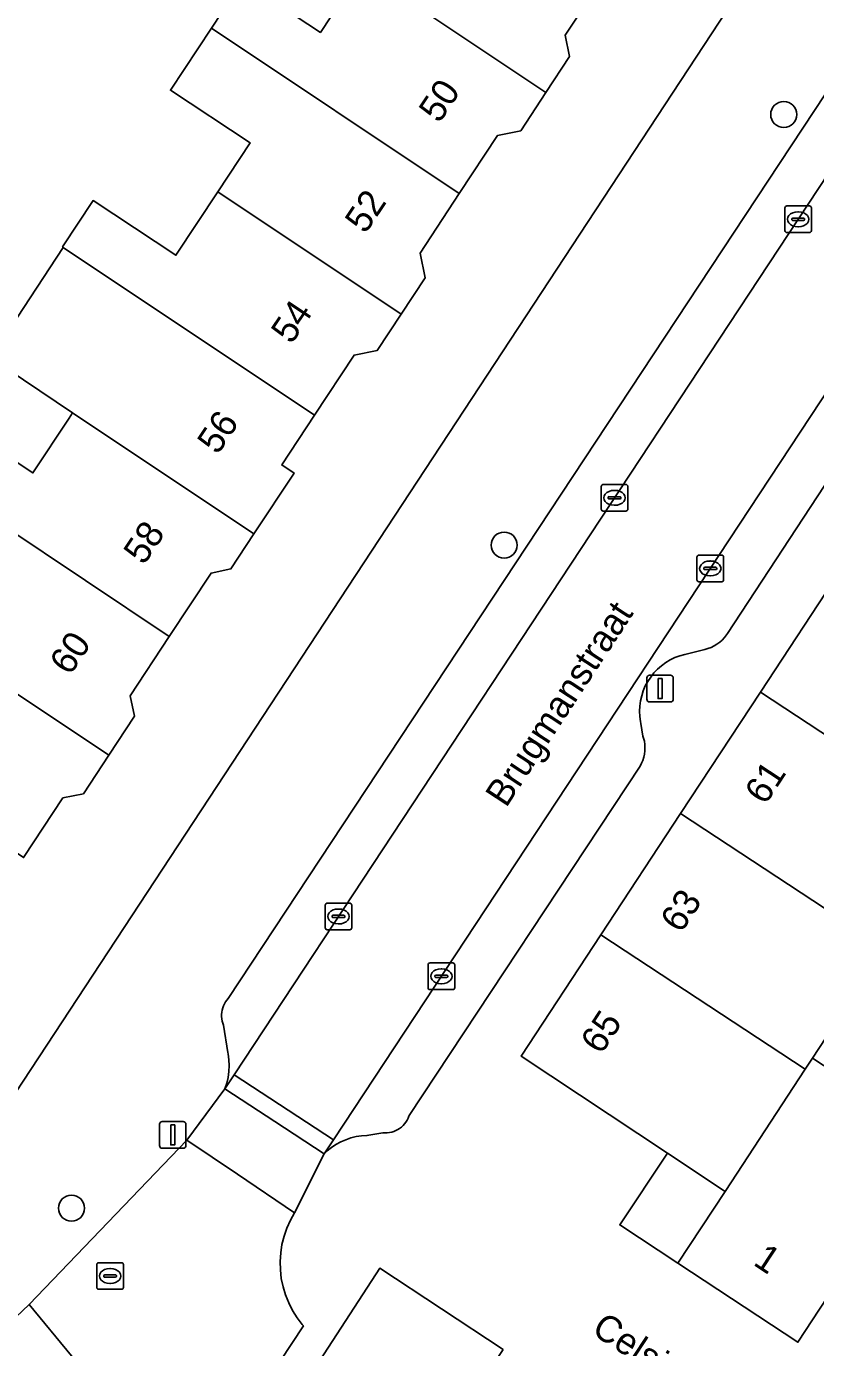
# Model space of a CAD drawing. Extents: x 159279 to 160377, y 384531 to 385888.
# Drawn here: x 159545.01 to 159574.65, y 385140.99 to 385190.61 of the extents above; entities that cross this region are included whole.
import ezdxf

# ---------------------------------------------------------------- set-up
doc = ezdxf.new("R2010")
doc.units = 0
for name, color, linetype in [('IMGEO_Boom', 7, 'Continuous'), ('IMGEO_Erf', 7, 'Continuous'), ('IMGEO_Kolk', 7, 'Continuous'), ('IMGEO_Lichtmast', 7, 'Continuous'), ('IMGEO_Openbare_ruimte_label', 7, 'Continuous'), ('IMGEO_Pand', 7, 'Continuous'), ('IMGEO_Pand_nummerreeks', 7, 'Continuous'), ('IMGEO_Parkeervlak_open', 7, 'Continuous'), ('IMGEO_Rijbaan_lokaal_open', 7, 'Continuous'), ('IMGEO_Rioolput', 7, 'Continuous'), ('IMGEO_Voetpad_open', 7, 'Continuous')]:
    doc.layers.add(name, color=color, linetype=linetype)

msp = doc.modelspace()

# ---------------------------------------------------------------- linework, layer by layer
at = {"layer": 'IMGEO_Boom'}
for centre in [(159573.455, 385187.303), (159562.957, 385171.13), (159546.706, 385146.226)]:
    msp.add_circle(centre, 0.489, dxfattribs=at)
at = {"layer": 'IMGEO_Erf'}
for points in [[(159535.013, 385135.989), (159573.94, 385195.196)], [(159542.165, 385175.88), (159545.258, 385173.842), (159546.615, 385175.901), (159546.747, 385176.101), (159543.665, 385178.161), (159546.4, 385182.31), (159546.373, 385182.328), (159547.52, 385184.068), (159550.63, 385182.019), (159552.2, 385184.401), (159553.414, 385186.243), (159550.423, 385188.213), (159551.959, 385190.544), (159553.128, 385192.317), (159556.057, 385190.387), (159557.613, 385192.749)], [(159566.634, 385192.38), (159565.25, 385190.281), (159565.415, 385189.479), (159564.526, 385188.13), (159563.58, 385186.695), (159562.71, 385186.516), (159561.27, 385184.331), (159559.799, 385182.098), (159559.989, 385181.172), (159559.087, 385179.803), (159558.191, 385178.443), (159557.322, 385178.265), (159555.833, 385176.006), (159554.604, 385174.141), (159555.067, 385173.836), (159553.559, 385171.548), (159552.694, 385170.235), (159551.949, 385170.082), (159550.378, 385167.697), (159548.911, 385165.471), (159549.07, 385164.7), (159548.106, 385163.236), (159547.154, 385161.792), (159546.382, 385161.634), (159544.907, 385159.396)], [(159579.919, 385180.874), (159571.346, 385167.81), (159571.309, 385167.756), (159571.23, 385167.657), (159571.143, 385167.565), (159571.049, 385167.482), (159570.947, 385167.407), (159570.839, 385167.342), (159570.725, 385167.287), (159570.607, 385167.242), (159570.486, 385167.208), (159569.738, 385167.026), (159569.549, 385166.973), (159569.366, 385166.903), (159569.189, 385166.818), (159569.021, 385166.717), (159568.863, 385166.601), (159568.715, 385166.471), (159568.58, 385166.329), (159568.458, 385166.176), (159568.35, 385166.012), (159568.257, 385165.839), (159568.18, 385165.659), (159568.12, 385165.472), (159568.076, 385165.281), (159568.05, 385165.086), (159568.041, 385164.89), (159568.049, 385164.694), (159568.076, 385164.5), (159568.09, 385164.427), (159568.168, 385163.957), (159568.192, 385163.882), (159568.22, 385163.764), (159568.237, 385163.643), (159568.244, 385163.522), (159568.24, 385163.401), (159568.225, 385163.28), (159568.199, 385163.162), (159568.163, 385163.046), (159568.116, 385162.934), (159568.06, 385162.826), (159559.386, 385149.711), (159559.376, 385149.681), (159559.346, 385149.604), (159559.308, 385149.529), (159559.264, 385149.458), (159559.214, 385149.392), (159559.158, 385149.33), (159559.097, 385149.273), (159559.031, 385149.223), (159558.961, 385149.178), (159558.887, 385149.139), (159558.81, 385149.108), (159558.731, 385149.083), (159558.649, 385149.066), (159558.566, 385149.056), (159558.483, 385149.053), (159558.4, 385149.058), (159557.804, 385148.953), (159557.6, 385148.942), (159557.398, 385148.912), (159557.199, 385148.864), (159557.006, 385148.799), (159556.819, 385148.717), (159556.64, 385148.618), (159556.47, 385148.504), (159556.312, 385148.375), (159556.2, 385148.269), (159555.083, 385146.052), (159554.926, 385145.772), (159554.794, 385145.479), (159554.689, 385145.176), (159554.612, 385144.865), (159554.563, 385144.547), (159554.542, 385144.227), (159554.55, 385143.906), (159554.586, 385143.587), (159554.651, 385143.273), (159554.744, 385142.966), (159554.864, 385142.668), (159555.01, 385142.382), (159555.181, 385142.11), (159555.375, 385141.855), (159555.415, 385141.808), (159553.225, 385138.493)], [(159574.804, 385142.432), (159573.988, 385141.19), (159569.482, 385144.159), (159567.296, 385145.599), (159569.09, 385148.289), (159563.593, 385151.939), (159566.588, 385156.495), (159569.583, 385161.052), (159572.578, 385165.608), (159575.573, 385170.164)], [(159577.258, 385156.006), (159574.54, 385151.865), (159579.054, 385148.896)], [(159553.263, 385136.243), (159558.284, 385143.967), (159562.915, 385140.917)]]:
    msp.add_lwpolyline(points, dxfattribs=at)
at = {"layer": 'IMGEO_Kolk'}
for p, q in [((159573.496, 385182.942), (159573.496, 385183.794)), ((159573.571, 385183.868), (159574.423, 385183.868)), ((159574.497, 385183.794), (159574.497, 385182.942)), ((159573.755, 385183.362), (159573.755, 385183.374)), ((159574.193, 385183.325), (159573.795, 385183.325)), ((159573.798, 385183.411), (159574.196, 385183.411)), ((159573.984, 385183.648), (159574.009, 385183.648)), ((159574.239, 385183.374), (159574.239, 385183.362)), ((159574.423, 385182.868), (159573.571, 385182.868)), ((159574.007, 385183.088), (159573.982, 385183.088)), ((159566.599, 385172.48), (159566.599, 385173.332)), ((159566.674, 385173.406), (159567.526, 385173.406)), ((159567.6, 385173.332), (159567.6, 385172.48)), ((159566.858, 385172.9), (159566.858, 385172.912)), ((159567.296, 385172.863), (159566.898, 385172.863)), ((159566.901, 385172.949), (159567.299, 385172.949)), ((159567.087, 385173.186), (159567.112, 385173.186)), ((159567.342, 385172.912), (159567.342, 385172.9)), ((159567.526, 385172.406), (159566.674, 385172.406)), ((159567.11, 385172.626), (159567.085, 385172.626)), ((159570.197, 385169.827), (159570.197, 385170.679)), ((159570.272, 385170.753), (159571.124, 385170.753)), ((159570.499, 385170.296), (159570.897, 385170.296)), ((159570.685, 385170.533), (159570.71, 385170.533)), ((159571.198, 385170.679), (159571.198, 385169.827)), ((159570.456, 385170.247), (159570.456, 385170.259)), ((159570.894, 385170.21), (159570.496, 385170.21)), ((159570.708, 385169.973), (159570.683, 385169.973)), ((159570.94, 385170.259), (159570.94, 385170.247)), ((159571.124, 385169.753), (159570.272, 385169.753)), ((159556.233, 385156.756), (159556.233, 385157.608)), ((159556.308, 385157.682), (159557.16, 385157.682)), ((159556.721, 385157.462), (159556.746, 385157.462)), ((159557.234, 385157.608), (159557.234, 385156.756)), ((159556.492, 385157.176), (159556.492, 385157.188)), ((159556.93, 385157.139), (159556.532, 385157.139)), ((159556.535, 385157.225), (159556.933, 385157.225)), ((159556.744, 385156.902), (159556.719, 385156.902)), ((159556.976, 385157.188), (159556.976, 385157.176)), ((159557.16, 385156.682), (159556.308, 385156.682)), ((159560.171, 385155.435), (159561.023, 385155.435)), ((159560.096, 385154.509), (159560.096, 385155.361)), ((159560.355, 385154.929), (159560.355, 385154.941)), ((159560.398, 385154.978), (159560.796, 385154.978)), ((159560.584, 385155.215), (159560.609, 385155.215)), ((159560.839, 385154.941), (159560.839, 385154.929)), ((159561.097, 385155.361), (159561.097, 385154.509)), ((159561.023, 385154.435), (159560.171, 385154.435)), ((159560.793, 385154.892), (159560.395, 385154.892)), ((159560.607, 385154.655), (159560.582, 385154.655))]:
    msp.add_line(p, q, dxfattribs=at)
for points in [[(159573.496, 385182.942), (159573.496, 385183.794)], [(159573.571, 385183.868), (159574.423, 385183.868)], [(159574.497, 385183.794), (159574.497, 385182.942)], [(159574.423, 385182.868), (159573.571, 385182.868)], [(159566.599, 385172.48), (159566.599, 385173.332)], [(159566.674, 385173.406), (159567.526, 385173.406)], [(159567.6, 385173.332), (159567.6, 385172.48)], [(159567.526, 385172.406), (159566.674, 385172.406)], [(159570.197, 385169.827), (159570.197, 385170.679)], [(159570.272, 385170.753), (159571.124, 385170.753)], [(159571.198, 385170.679), (159571.198, 385169.827)], [(159571.124, 385169.753), (159570.272, 385169.753)], [(159556.233, 385156.756), (159556.233, 385157.608)], [(159556.308, 385157.682), (159557.16, 385157.682)], [(159557.234, 385157.608), (159557.234, 385156.756)], [(159557.16, 385156.682), (159556.308, 385156.682)], [(159560.171, 385155.435), (159561.023, 385155.435)], [(159560.096, 385154.509), (159560.096, 385155.361)], [(159561.097, 385155.361), (159561.097, 385154.509)], [(159561.023, 385154.435), (159560.171, 385154.435)]]:
    msp.add_lwpolyline(points, dxfattribs=at)
for centre, radius, start, end in [((159573.573, 385183.792), 0.0765, 91.552, 178.448), ((159573.573, 385183.792), 0.0765, 91.552, 178.448), ((159574.421, 385183.792), 0.0765, 1.552, 88.448), ((159574.421, 385183.792), 0.0765, 1.552, 88.448), ((159573.795, 385183.371), 0.0403, 85.8775, 175.7526), ((159573.792, 385183.361), 0.0366, 178.938, 274.7102), ((159574.196, 385183.368), 0.043, 264.8664, 352.4533), ((159574.2, 385183.373), 0.0386, 1.7309, 96.639), ((159573.573, 385182.944), 0.0765, 181.552, 268.448), ((159573.573, 385182.944), 0.0765, 181.552, 268.448), ((159574.421, 385182.944), 0.0765, 271.552, 358.448), ((159574.421, 385182.944), 0.0765, 271.552, 358.448), ((159566.676, 385173.33), 0.0765, 91.552, 178.448), ((159566.676, 385173.33), 0.0765, 91.552, 178.448), ((159567.524, 385173.33), 0.0765, 1.552, 88.448), ((159567.524, 385173.33), 0.0765, 1.552, 88.448), ((159566.898, 385172.909), 0.0403, 85.8775, 175.7526), ((159566.895, 385172.899), 0.0366, 178.938, 274.7102), ((159567.299, 385172.906), 0.043, 264.8664, 352.4533), ((159567.303, 385172.911), 0.0386, 1.7309, 96.639), ((159566.676, 385172.482), 0.0765, 181.552, 268.448), ((159566.676, 385172.482), 0.0765, 181.552, 268.448), ((159567.524, 385172.482), 0.0765, 271.552, 358.448), ((159567.524, 385172.482), 0.0765, 271.552, 358.448), ((159570.274, 385170.677), 0.0765, 91.552, 178.448), ((159570.274, 385170.677), 0.0765, 91.552, 178.448), ((159570.496, 385170.256), 0.0403, 85.8775, 175.7526), ((159570.901, 385170.258), 0.0386, 1.7309, 96.639), ((159571.122, 385170.677), 0.0765, 1.552, 88.448), ((159571.122, 385170.677), 0.0765, 1.552, 88.448), ((159570.274, 385169.829), 0.0765, 181.552, 268.448), ((159570.274, 385169.829), 0.0765, 181.552, 268.448), ((159570.493, 385170.246), 0.0366, 178.938, 274.7102), ((159570.897, 385170.253), 0.043, 264.8664, 352.4533), ((159571.122, 385169.829), 0.0765, 271.552, 358.448), ((159571.122, 385169.829), 0.0765, 271.552, 358.448), ((159556.31, 385157.606), 0.0765, 91.552, 178.448), ((159556.31, 385157.606), 0.0765, 91.552, 178.448), ((159557.158, 385157.606), 0.0765, 1.552, 88.448), ((159557.158, 385157.606), 0.0765, 1.552, 88.448), ((159556.532, 385157.185), 0.0403, 85.8775, 175.7526), ((159556.529, 385157.175), 0.0366, 178.938, 274.7102), ((159556.933, 385157.182), 0.043, 264.8664, 352.4533), ((159556.937, 385157.187), 0.0386, 1.7309, 96.639), ((159556.31, 385156.758), 0.0765, 181.552, 268.448), ((159556.31, 385156.758), 0.0765, 181.552, 268.448), ((159557.158, 385156.758), 0.0765, 271.552, 358.448), ((159557.158, 385156.758), 0.0765, 271.552, 358.448), ((159560.173, 385155.359), 0.0765, 91.552, 178.448), ((159560.173, 385155.359), 0.0765, 91.552, 178.448), ((159561.021, 385155.359), 0.0765, 1.552, 88.448), ((159561.021, 385155.359), 0.0765, 1.552, 88.448), ((159560.395, 385154.938), 0.0403, 85.8775, 175.7526), ((159560.392, 385154.928), 0.0366, 178.938, 274.7102), ((159560.796, 385154.935), 0.043, 264.8664, 352.4533), ((159560.8, 385154.94), 0.0386, 1.7309, 96.639), ((159560.173, 385154.511), 0.0765, 181.552, 268.448), ((159560.173, 385154.511), 0.0765, 181.552, 268.448), ((159561.021, 385154.511), 0.0765, 271.552, 358.448), ((159561.021, 385154.511), 0.0765, 271.552, 358.448)]:
    msp.add_arc(centre, radius, start, end, dxfattribs=at)
for centre, major_axis, ratio, start_param, end_param in [((159573.983, 385183.368), (-0.387, 0.002), 0.722429, 4.712389, 7.853982), ((159574.008, 385183.368), (-0.39, 0.002), 0.717154, 1.570796, 4.712389), ((159567.086, 385172.906), (-0.387, 0.002), 0.722429, 4.712389, 7.853982), ((159567.111, 385172.906), (-0.39, 0.002), 0.717154, 1.570796, 4.712389), ((159570.684, 385170.253), (-0.387, 0.002), 0.722429, 4.712389, 7.853982), ((159570.709, 385170.253), (-0.39, 0.002), 0.717154, 1.570796, 4.712389), ((159556.72, 385157.182), (-0.387, 0.002), 0.722429, 4.712389, 7.853982), ((159556.745, 385157.182), (-0.39, 0.002), 0.717154, 1.570796, 4.712389), ((159560.583, 385154.935), (-0.387, 0.002), 0.722429, 4.712389, 7.853982), ((159560.608, 385154.935), (-0.39, 0.002), 0.717154, 1.570796, 4.712389)]:
    msp.add_ellipse(centre, major_axis=major_axis, ratio=ratio, start_param=start_param, end_param=end_param, dxfattribs=at)
at = {"layer": 'IMGEO_Lichtmast'}
for p, q in [((159568.315, 385165.339), (159568.315, 385166.139)), ((159568.315, 385166.139), (159568.315, 385165.339)), ((159568.415, 385166.239), (159569.205, 385166.239)), ((159569.205, 385166.239), (159568.415, 385166.239)), ((159569.305, 385166.139), (159569.305, 385165.339)), ((159569.305, 385165.339), (159569.305, 385166.139)), ((159569.205, 385165.239), (159568.415, 385165.239)), ((159568.415, 385165.239), (159569.205, 385165.239)), ((159550.113, 385149.476), (159550.903, 385149.476)), ((159550.903, 385149.476), (159550.113, 385149.476)), ((159550.013, 385148.576), (159550.013, 385149.376)), ((159550.013, 385149.376), (159550.013, 385148.576)), ((159551.003, 385149.376), (159551.003, 385148.576)), ((159551.003, 385148.576), (159551.003, 385149.376)), ((159550.903, 385148.476), (159550.113, 385148.476)), ((159550.113, 385148.476), (159550.903, 385148.476))]:
    msp.add_line(p, q, dxfattribs=at)
for points in [[(159568.735, 385166.114), (159568.885, 385166.114), (159568.885, 385165.364), (159568.735, 385165.364), (159568.735, 385166.114)], [(159550.433, 385149.351), (159550.583, 385149.351), (159550.583, 385148.601), (159550.433, 385148.601), (159550.433, 385149.351)]]:
    msp.add_lwpolyline(points, dxfattribs=at)
for centre, start, end in [((159568.415, 385166.139), 90, 180), ((159568.415, 385166.139), 90, 180), ((159569.205, 385166.139), 0, 90), ((159569.205, 385166.139), 360, 90), ((159568.415, 385165.339), 180, 270), ((159568.415, 385165.339), 180, 270), ((159569.205, 385165.339), 270, 0), ((159569.205, 385165.339), 270, 0), ((159550.113, 385149.376), 90, 180), ((159550.113, 385149.376), 90, 180), ((159550.903, 385149.376), 0, 90), ((159550.903, 385149.376), 360, 90), ((159550.113, 385148.576), 180, 270), ((159550.113, 385148.576), 180, 270), ((159550.903, 385148.576), 270, 0), ((159550.903, 385148.576), 270, 0)]:
    msp.add_arc(centre, 0.1, start, end, dxfattribs=at)
at = {"layer": 'IMGEO_Pand'}
for points in [[(159564.526, 385188.13), (159565.415, 385189.479), (159565.25, 385190.281), (159566.634, 385192.38), (159567.121, 385192.059), (159567.265, 385192.277), (159557.315, 385198.926), (159556.995, 385198.453), (159555.791, 385196.632), (159558.846, 385194.619), (159557.613, 385192.749)], [(159557.613, 385192.749), (159556.057, 385190.387), (159553.128, 385192.317), (159551.959, 385190.544), (159561.27, 385184.331), (159562.71, 385186.516), (159563.58, 385186.695), (159564.526, 385188.13)], [(159551.959, 385190.544), (159550.423, 385188.213), (159553.414, 385186.243), (159552.2, 385184.401), (159559.087, 385179.803), (159559.989, 385181.172), (159559.799, 385182.098), (159561.27, 385184.331)], [(159552.2, 385184.401), (159550.63, 385182.019), (159547.52, 385184.068), (159546.373, 385182.328), (159546.4, 385182.31), (159555.833, 385176.006), (159557.322, 385178.265), (159558.191, 385178.443), (159559.087, 385179.803)], [(159546.4, 385182.31), (159543.665, 385178.161), (159546.747, 385176.101), (159553.559, 385171.548), (159555.067, 385173.836), (159554.604, 385174.141), (159555.833, 385176.006)], [(159546.747, 385176.101), (159546.615, 385175.901), (159545.258, 385173.842), (159542.165, 385175.88), (159540.932, 385174.01), (159550.378, 385167.697), (159551.949, 385170.082), (159552.694, 385170.235), (159553.559, 385171.548)], [(159540.932, 385174.01), (159539.456, 385171.77), (159538.197, 385169.859), (159541.235, 385167.828), (159548.106, 385163.236), (159549.07, 385164.7), (159548.911, 385165.471), (159550.378, 385167.697)], [(159538.197, 385169.859), (159536.659, 385167.525), (159535.462, 385165.708), (159544.907, 385159.396), (159546.382, 385161.634), (159547.154, 385161.792), (159548.106, 385163.236), (159541.235, 385167.828)], [(159575.573, 385170.164), (159572.578, 385165.608), (159580.25, 385160.565), (159583.242, 385165.123)], [(159572.578, 385165.608), (159569.583, 385161.052), (159577.258, 385156.006), (159580.25, 385160.565)], [(159569.583, 385161.052), (159566.588, 385156.495), (159574.266, 385151.448), (159574.54, 385151.865), (159577.258, 385156.006)], [(159574.266, 385151.448), (159566.588, 385156.495), (159563.593, 385151.939), (159569.09, 385148.289), (159571.251, 385146.854)], [(159579.054, 385148.896), (159574.54, 385151.865), (159574.266, 385151.448), (159571.251, 385146.854), (159569.482, 385144.159), (159573.988, 385141.19), (159574.804, 385142.432)], [(159571.251, 385146.854), (159569.09, 385148.289), (159567.296, 385145.599), (159569.482, 385144.159)], [(159562.915, 385140.917), (159558.284, 385143.967), (159553.263, 385136.243), (159557.849, 385133.227)]]:
    msp.add_lwpolyline(points, close=True, dxfattribs=at)
at = {"layer": 'IMGEO_Parkeervlak_open'}
for points in [[(159575.457, 385188.748), (159552.596, 385154.106), (159552.542, 385154.043), (159552.493, 385153.975), (159552.451, 385153.903), (159552.415, 385153.828), (159552.387, 385153.75), (159552.365, 385153.669), (159552.35, 385153.587), (159552.343, 385153.504), (159552.344, 385153.421), (159552.352, 385153.338), (159552.367, 385153.256), (159552.39, 385153.176), (159552.419, 385153.098), (159552.581, 385152.074), (159552.59, 385152.024), (159552.619, 385151.803), (159552.629, 385151.579), (159552.618, 385151.356), (159552.587, 385151.134), (159552.537, 385150.916), (159552.467, 385150.704), (159552.814, 385151.23), (159578.102, 385189.592)], [(159579.793, 385184.048), (159556.547, 385148.795), (159556.2, 385148.269), (159556.312, 385148.375), (159556.47, 385148.504), (159556.64, 385148.618), (159556.819, 385148.717), (159557.006, 385148.799), (159557.199, 385148.864), (159557.398, 385148.912), (159557.6, 385148.942), (159557.804, 385148.953), (159558.4, 385149.058), (159558.483, 385149.053), (159558.566, 385149.056), (159558.649, 385149.066), (159558.731, 385149.083), (159558.81, 385149.108), (159558.887, 385149.139), (159558.961, 385149.178), (159559.031, 385149.223), (159559.097, 385149.273), (159559.158, 385149.33), (159559.214, 385149.392), (159559.264, 385149.458), (159559.308, 385149.529), (159559.346, 385149.604), (159559.376, 385149.681), (159559.386, 385149.711), (159568.06, 385162.826), (159568.116, 385162.934), (159568.163, 385163.046), (159568.199, 385163.162), (159568.225, 385163.28), (159568.24, 385163.401), (159568.244, 385163.522), (159568.237, 385163.643), (159568.22, 385163.764), (159568.192, 385163.882), (159568.168, 385163.957), (159568.09, 385164.427), (159568.076, 385164.5), (159568.049, 385164.694), (159568.041, 385164.89), (159568.05, 385165.086), (159568.076, 385165.281), (159568.12, 385165.472), (159568.18, 385165.659), (159568.257, 385165.839), (159568.35, 385166.012), (159568.458, 385166.176), (159568.58, 385166.329), (159568.715, 385166.471), (159568.863, 385166.601), (159569.021, 385166.717), (159569.189, 385166.818), (159569.366, 385166.903), (159569.549, 385166.973), (159569.738, 385167.026), (159570.486, 385167.208), (159570.607, 385167.242), (159570.725, 385167.287), (159570.839, 385167.342), (159570.947, 385167.407), (159571.049, 385167.482), (159571.143, 385167.565), (159571.23, 385167.657), (159571.309, 385167.756), (159571.346, 385167.81), (159579.919, 385180.874)]]:
    msp.add_lwpolyline(points, dxfattribs=at)
at = {"layer": 'IMGEO_Rijbaan_lokaal_open'}
for points in [[(159579.793, 385184.048), (159581.809, 385187.106), (159578.102, 385189.592), (159552.814, 385151.23), (159556.547, 385148.795)], [(159552.467, 385150.704), (159554.342, 385149.481), (159556.2, 385148.269), (159556.547, 385148.795), (159552.814, 385151.23)], [(159554.342, 385149.481), (159552.467, 385150.704), (159551.035, 385148.782), (159552.935, 385147.5), (159555.083, 385146.052), (159556.2, 385148.269)]]:
    msp.add_lwpolyline(points, close=True, dxfattribs=at)
msp.add_lwpolyline([(159553.225, 385138.493), (159555.415, 385141.808), (159555.375, 385141.855), (159555.181, 385142.11), (159555.01, 385142.382), (159554.864, 385142.668), (159554.744, 385142.966), (159554.651, 385143.273), (159554.586, 385143.587), (159554.55, 385143.906), (159554.542, 385144.227), (159554.563, 385144.547), (159554.612, 385144.865), (159554.689, 385145.176), (159554.794, 385145.479), (159554.926, 385145.772), (159555.083, 385146.052), (159552.935, 385147.5), (159551.035, 385148.782), (159545.121, 385142.605), (159546.712, 385140.681)], dxfattribs=at)
at = {"layer": 'IMGEO_Rioolput'}
for p, q in [((159547.656, 385143.253), (159547.656, 385144.105)), ((159547.731, 385144.179), (159548.583, 385144.179)), ((159548.657, 385144.105), (159548.657, 385143.253)), ((159547.915, 385143.673), (159547.915, 385143.685)), ((159548.353, 385143.636), (159547.955, 385143.636)), ((159547.958, 385143.722), (159548.356, 385143.722)), ((159548.144, 385143.959), (159548.169, 385143.959)), ((159548.399, 385143.685), (159548.399, 385143.673)), ((159548.583, 385143.179), (159547.731, 385143.179)), ((159548.167, 385143.399), (159548.142, 385143.399))]:
    msp.add_line(p, q, dxfattribs=at)
for points in [[(159547.656, 385143.253), (159547.656, 385144.105)], [(159547.731, 385144.179), (159548.583, 385144.179)], [(159548.657, 385144.105), (159548.657, 385143.253)], [(159548.583, 385143.179), (159547.731, 385143.179)]]:
    msp.add_lwpolyline(points, dxfattribs=at)
for centre, radius, start, end in [((159547.733, 385144.103), 0.0765, 91.552, 178.448), ((159547.733, 385144.103), 0.0765, 91.552, 178.448), ((159548.581, 385144.103), 0.0765, 1.552, 88.448), ((159548.581, 385144.103), 0.0765, 1.552, 88.448), ((159547.955, 385143.682), 0.0403, 85.8775, 175.7526), ((159547.952, 385143.672), 0.0366, 178.938, 274.7102), ((159548.356, 385143.679), 0.043, 264.8664, 352.4533), ((159548.36, 385143.684), 0.0386, 1.7309, 96.639), ((159547.733, 385143.255), 0.0765, 181.552, 268.448), ((159547.733, 385143.255), 0.0765, 181.552, 268.448), ((159548.581, 385143.255), 0.0765, 271.552, 358.448), ((159548.581, 385143.255), 0.0765, 271.552, 358.448)]:
    msp.add_arc(centre, radius, start, end, dxfattribs=at)
for centre, major_axis, ratio, start_param, end_param in [((159548.143, 385143.679), (-0.387, 0.002), 0.722429, 4.712389, 7.853982), ((159548.168, 385143.679), (-0.39, 0.002), 0.717154, 1.570796, 4.712389)]:
    msp.add_ellipse(centre, major_axis=major_axis, ratio=ratio, start_param=start_param, end_param=end_param, dxfattribs=at)
at = {"layer": 'IMGEO_Voetpad_open'}
for points in [[(159573.94, 385195.196), (159535.013, 385135.989), (159534.234, 385134.804), (159531.987, 385136.276), (159528.55, 385131.062), (159513.409, 385118.571)], [(159552.629, 385151.579), (159552.619, 385151.803), (159552.59, 385152.024), (159552.581, 385152.074), (159552.419, 385153.098), (159552.39, 385153.176), (159552.367, 385153.256), (159552.352, 385153.338), (159552.344, 385153.421), (159552.343, 385153.504), (159552.35, 385153.587), (159552.365, 385153.669), (159552.387, 385153.75), (159552.415, 385153.828), (159552.451, 385153.903), (159552.493, 385153.975), (159552.542, 385154.043), (159552.596, 385154.106), (159575.457, 385188.748)], [(159509.932, 385118.983), (159504.55, 385114.528), (159507.347, 385111.146), (159507.439, 385111.212), (159507.575, 385111.323), (159508.785, 385112.295), (159511.351, 385114.434), (159513.826, 385116.492), (159526.239, 385126.771), (159525.927, 385127.153), (159528.846, 385129.572), (159529.162, 385129.185), (159542.862, 385140.537), (159543.347, 385140.939), (159545.121, 385142.605), (159551.035, 385148.782), (159552.467, 385150.704), (159552.537, 385150.916), (159552.587, 385151.134), (159552.618, 385151.356), (159552.629, 385151.579)]]:
    msp.add_lwpolyline(points, dxfattribs=at)
msp.add_lwpolyline([(159553.225, 385138.493), (159552.781, 385138.729), (159552.318, 385138.925), (159551.84, 385139.078), (159551.349, 385139.188), (159550.851, 385139.254), (159550.349, 385139.275), (159549.847, 385139.252), (159549.349, 385139.183), (159548.859, 385139.07), (159548.381, 385138.914), (159548.224, 385138.852), (159546.712, 385140.681), (159545.121, 385142.605), (159543.347, 385140.939), (159544.838, 385139.116), (159546.248, 385137.391), (159549.148, 385136.186)], close=True, dxfattribs=at)

# ---------------------------------------------------------------- texts
at = {"layer": 'IMGEO_Openbare_ruimte_label'}
for s, rotation, p in [('Brugmanstraat', 56.7865, (159563.029, 385161.237)), ('Celsiusstraat', 326.7551, (159566.194, 385141.538))]:
    msp.add_text(s, height=1, rotation=rotation, dxfattribs=at).set_placement(p)
at = {"layer": 'IMGEO_Pand_nummerreeks'}
for s, rotation, p in [('50', 56.2415, (159560.517, 385186.94)), ('52', 56.2415, (159557.741, 385182.787)), ('54', 56.2415, (159554.969, 385178.64)), ('56', 56.2415, (159552.196, 385174.491)), ('58', 56.2415, (159549.425, 385170.346)), ('60', 56.2415, (159546.652, 385166.197)), ('61', 56.6827, (159572.761, 385161.335)), ('63', 56.6827, (159569.595, 385156.519)), ('65', 56.6827, (159566.599, 385151.961)), ('1', 326.6195, (159572.267, 385144.121))]:
    msp.add_text(s, height=1, rotation=rotation, dxfattribs=at).set_placement(p)

doc.saveas('drawing.dxf')
